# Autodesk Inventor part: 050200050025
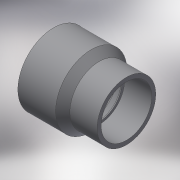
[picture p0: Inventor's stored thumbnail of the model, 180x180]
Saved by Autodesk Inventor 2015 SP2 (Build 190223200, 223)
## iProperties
Created: 2017-10
Part Number: 050200050025
Material: Generic
Description: PLASSON REDUCING SOCKET M.F.50(40)25 CEMENTED
Document SubType Name: Modeling
Designer: KIM
Density: 1 g/cm^3
Appearance: Default
Author: KIM
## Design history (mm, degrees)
derived "050200.ipt"
feature "Solid1::050200.ipt"
tag "TaggingFeature1"
body "Solid1"
other parameters: "d0" = 62, "d1" = 31, "d2" = 19, "d3" = 26, "d4" = 25, "d5" = 33, "d8" = 22.5, "d9" = 45 deg, "d12" = 0.4, "d_1" = 25, "L_" = 31, "l_" = 26, "l_1" = 19, "E_" = 33, "H_" = 62, "d11" = 6.16297
